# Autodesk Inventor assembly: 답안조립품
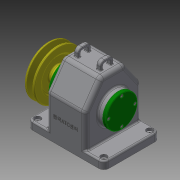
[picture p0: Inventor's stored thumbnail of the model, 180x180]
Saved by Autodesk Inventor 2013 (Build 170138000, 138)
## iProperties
Created: 2016-12
Part Number: 답안조립품
Document SubType Name: Assembly
Designer: Administrator
Author: Administrator
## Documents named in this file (15)
- C:\Users\Administrator\Desktop\461208V1030\답안조립품.iam
- C:\Users\Administrator\Desktop\461208V1030\V-벨트풀리.ipt
- C:\Users\Administrator\Desktop\461208V1030\뒤커버.ipt
- C:\Users\Administrator\Desktop\461208V1030\멈춤나사 - M4x10.ipt
- C:\Users\Administrator\Desktop\461208V1030\베어링 6203.ipt
- C:\Users\Administrator\Desktop\461208V1030\본체.ipt
- C:\Users\Administrator\Desktop\461208V1030\볼트 M3 x 8.ipt
- C:\Users\Administrator\Desktop\461208V1030\볼트 M3 x 10.ipt
- C:\Users\Administrator\Desktop\461208V1030\부시.ipt
- C:\Users\Administrator\Desktop\461208V1030\스퍼기어.ipt
- C:\Users\Administrator\Desktop\461208V1030\앞커버.ipt
- C:\Users\Administrator\Desktop\461208V1030\오일씰 28 40 8.ipt
- C:\Users\Administrator\Desktop\461208V1030\축.ipt
- C:\Users\Administrator\Desktop\461208V1030\키 - 5 x 5 x 18.ipt
- C:\Users\Administrator\Desktop\461208V1030\키 - 6 x 6 x 22.ipt
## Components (9 placed, 3 different names)
1. V-벨트풀리:1
2. ISO 4762 M3 x 10:1
3. ISO 4762 M3 x 10:2
4. ISO 4762 M3 x 10:3
5. ISO 4762 M3 x 10:4
6. ISO 4762 M3 x 8:1
7. ISO 4762 M3 x 8:2
8. ISO 4762 M3 x 8:3
9. ISO 4762 M3 x 8:4
